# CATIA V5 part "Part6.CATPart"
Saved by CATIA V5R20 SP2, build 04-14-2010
Part number: Part4.1
Bounding box of the stored display mesh (mm): x 0 to 35, y -14.119 to 167.761, z 82.437 to 124.337
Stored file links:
  E:\CATIA\New folder\Part6.CATPart
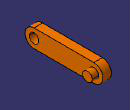
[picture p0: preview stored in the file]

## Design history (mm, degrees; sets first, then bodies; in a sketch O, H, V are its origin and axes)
Body1 (main body)
  Sketch1 on yz-plane, origin (0, 0, 0), H (0, 1, 0), V (0, 0, 1)
    construction line L1 (6.8209, 103.3865) -> (146.8209, 103.3865)
    line L2 (6.8209, 124.3365) -> (146.8209, 124.3365)
    line L3 (146.8209, 82.4365) -> (6.8209, 82.4365)
    arc A1 centre (146.8209, 103.3865) radius 20.95 from (146.8209, 124.3365) to (146.8209, 82.4365) cw
    arc A2 centre (6.8209, 103.3865) radius 20.95 from (6.8209, 82.4365) to (6.8209, 124.3365) cw
    circle A3 centre (146.8209, 103.3865) radius 11.04
    circle A4 centre (6.8209, 103.3865) radius 11.04
  MultiPad1: profile Sketch1, domains (length 20; length 0; length 35)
